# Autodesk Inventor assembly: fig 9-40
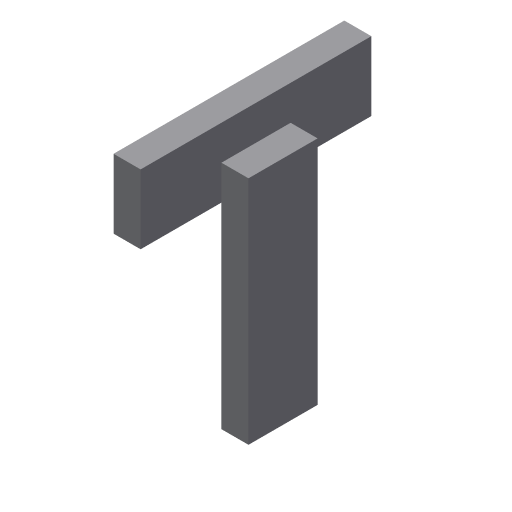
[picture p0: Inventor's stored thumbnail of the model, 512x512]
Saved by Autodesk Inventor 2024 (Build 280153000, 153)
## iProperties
Created: 2013-07
Part Number: fig 9-40
Document SubType Name: Assembly
Designer: CADCIM
Author: CADCIM
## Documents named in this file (2)
- D:\PROJECTS\Project 2023\RESOURCES INVENTOR 2024\RESOURCES INVENTOR 2024\Inventor_2023_Part\Inventor_2024_Part\c09_Inv_2024_prt\fig 9-41.iam
- D:\PROJECTS\Project 2023\RESOURCES INVENTOR 2024\RESOURCES INVENTOR 2024\Inventor_2023_Part\Inventor_2024_Part\c09_Inv_2024_prt\12.ipt
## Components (2 placed, 1 different names)
1. 12:1 — Rigid:1
2. 12:2 — Rigid:1
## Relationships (1: WeldJoint 1)
- Rigid:1 [WeldJoint]: 12:1 ↔ 12:2
